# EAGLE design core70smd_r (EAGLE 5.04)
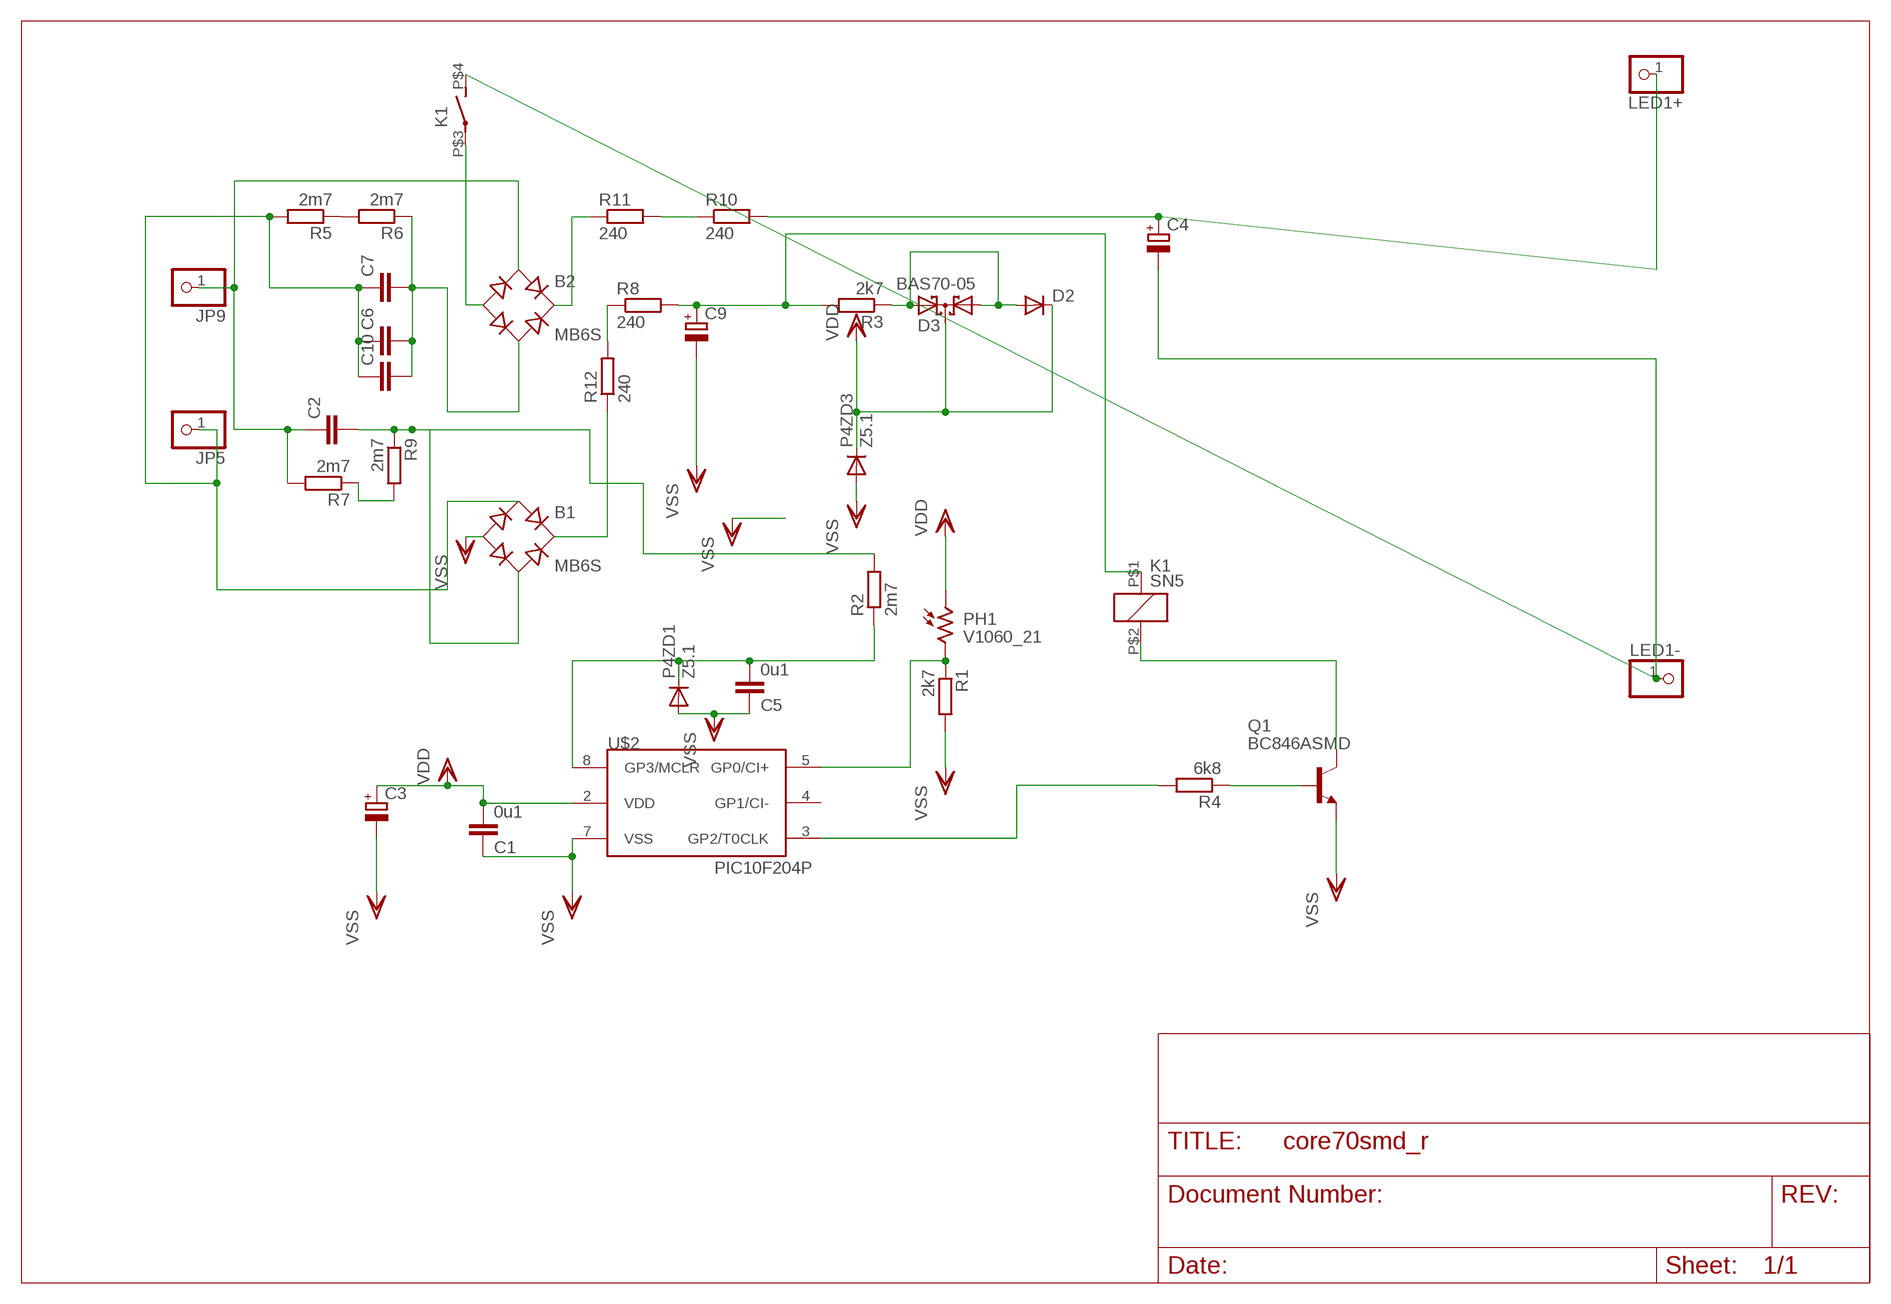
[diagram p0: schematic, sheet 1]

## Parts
B1  MB6S  [SOIC-4]
B2  MB6S  [SOIC-4]
C1  0u1  C-EUC1206  [C1206]
C2  C-EUC4564  [C4564]
C3  CPOL-EUD  [PANASONIC_D]
C4  CPOL-EUSMCE  [SMC_E]
C5  0u1  C-EUC1206  [C1206]
C6  C-EUC4564  [C4564]
C7  C-EUC4564  [C4564]
C9  CPOL-EUSMCD  [SMC_D]
C10  C-EUC4564  [C4564]
D2  DIODE-MINIMELF  [MINIMELF]
D3  BAS70-05  [SOT23]
JP5  PINHD-1X1  [1X01]
JP9  PINHD-1X1  [1X01]
K1  SN5  [HU]
LED1+  PINHD-1X1  [1X01]
LED1-  PINHD-1X1  [1X01]
P4ZD1  Z5.1  DIODE-MINIMELF  [MINIMELF]
P4ZD3  Z5.1  DIODE-MINIMELF  [MINIMELF]
PH1  V1060_21  [TO-5_V10]
Q1  BC846ASMD  [SOT23]
R1  2k7  R-EU_R1206  [R1206]
R2  2m7  R-EU_R1206  [R1206]
R3  2k7  R-EU_MELF0207R  [MINI_MELF-0207R]
R4  6k8  R-EU_R1206  [R1206]
R5  2m7  R-EU_R1210  [R1210]
R6  2m7  R-EU_R1210  [R1210]
R7  2m7  R-EU_R1210  [R1210]
R8  240  R-EU_R1210  [R1210]
R9  2m7  R-EU_R1210  [R1210]
R10  240  R-EU_R2010  [R2010]
R11  240  R-EU_R2010  [R2010]
R12  240  R-EU_R1210  [R1210]
U$2  PIC10F204P  [DIL8]

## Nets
AC1: B1.~1(AC1) C6.1 C7.1 C10.1 JP5.1 R5.2
AC2: B2.~1(AC1) C2.1 JP9.1 R7.2
CBIG: B2.~2(AC2) C6.2 C7.2 C10.2 R6.1
CSMALL: B1.~2(AC2) C2.2 R2.2 R9.1
D+: C4.+ LED1+.1 R10.2
D-: C4.- K1.P$4(2:S) LED1-.1
DR+: C9.+ K1.P$1 R3.2 R8.2
N$1: C5.2 P4ZD1.C R2.1 U$2.8(GP3/MCLR)
N$2: R5.1 R6.2
N$3: R7.1 R9.2
N$4: R8.1 R12.2
N$5: D2.A D3.1(A1) D3.2(A2) R3.1
N$6: R10.1 R11.2
N$9: B2.- K1.P$3(2:P)
N$11: B2.+ R11.1
N$12: Q1.1(B) R4.1
N$13: K1.P$2 Q1.3(C)
N$15: R4.2 U$2.3(GP2/T0CLK)
N$17: PH1.2 R1.1 U$2.5(GP0/CI+)
RECDR+: B1.+ R12.1
VDD: C1.2 C3.+ D2.C D3.3(C) P4ZD3.C PH1.1 U$2.2(VDD)
VSS: B1.- C1.1 C3.- C5.1 C9.- P4ZD1.A P4ZD3.A Q1.2(E) R1.2 U$2.7(VSS)
Unconnected: U$2.4(GP1/CI-)

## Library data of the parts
B1 B2 = rectifier:MB*S: Bridge Rectifier Source: http://www.fairchildsemi.com/ds/MB/MB6S.pdf
C1 C5 = rcl:C-EU: CAPACITOR, European symbol
C2 C6 C7 C10 = rcl-2:C-EU: CAPACITOR, European symbol
C3 C4 C9 = rcl-2:CPOL-EU: POLARIZED CAPACITOR, European symbol
D2 P4ZD1 P4ZD3 = diode:DIODE-: DIODE
D3 = diode:BAS70-05: Silicon Schottky Diodes General-purpose diode for high-speed switching
JP5 JP9 LED1+ LED1- = pinhead(2):PINHD-1X1: PIN HEADER
K1 = relay:SN*: Slim PCB Relay 1 pole 6 A SCHRACK Source: http://www.schrack.com/.. 5815.pdf
PH1 = photo-elements:?1060*: Sensor Street Light control
Q1 = transistor-npn:BC846*: NPN Transistor
R1-R12 = rcl-2:R-EU_: RESISTOR, European symbol
U$2 = microchip-3:PIC10F2*: uPC nW 0,25/0,5k Program Flash memory Comparator

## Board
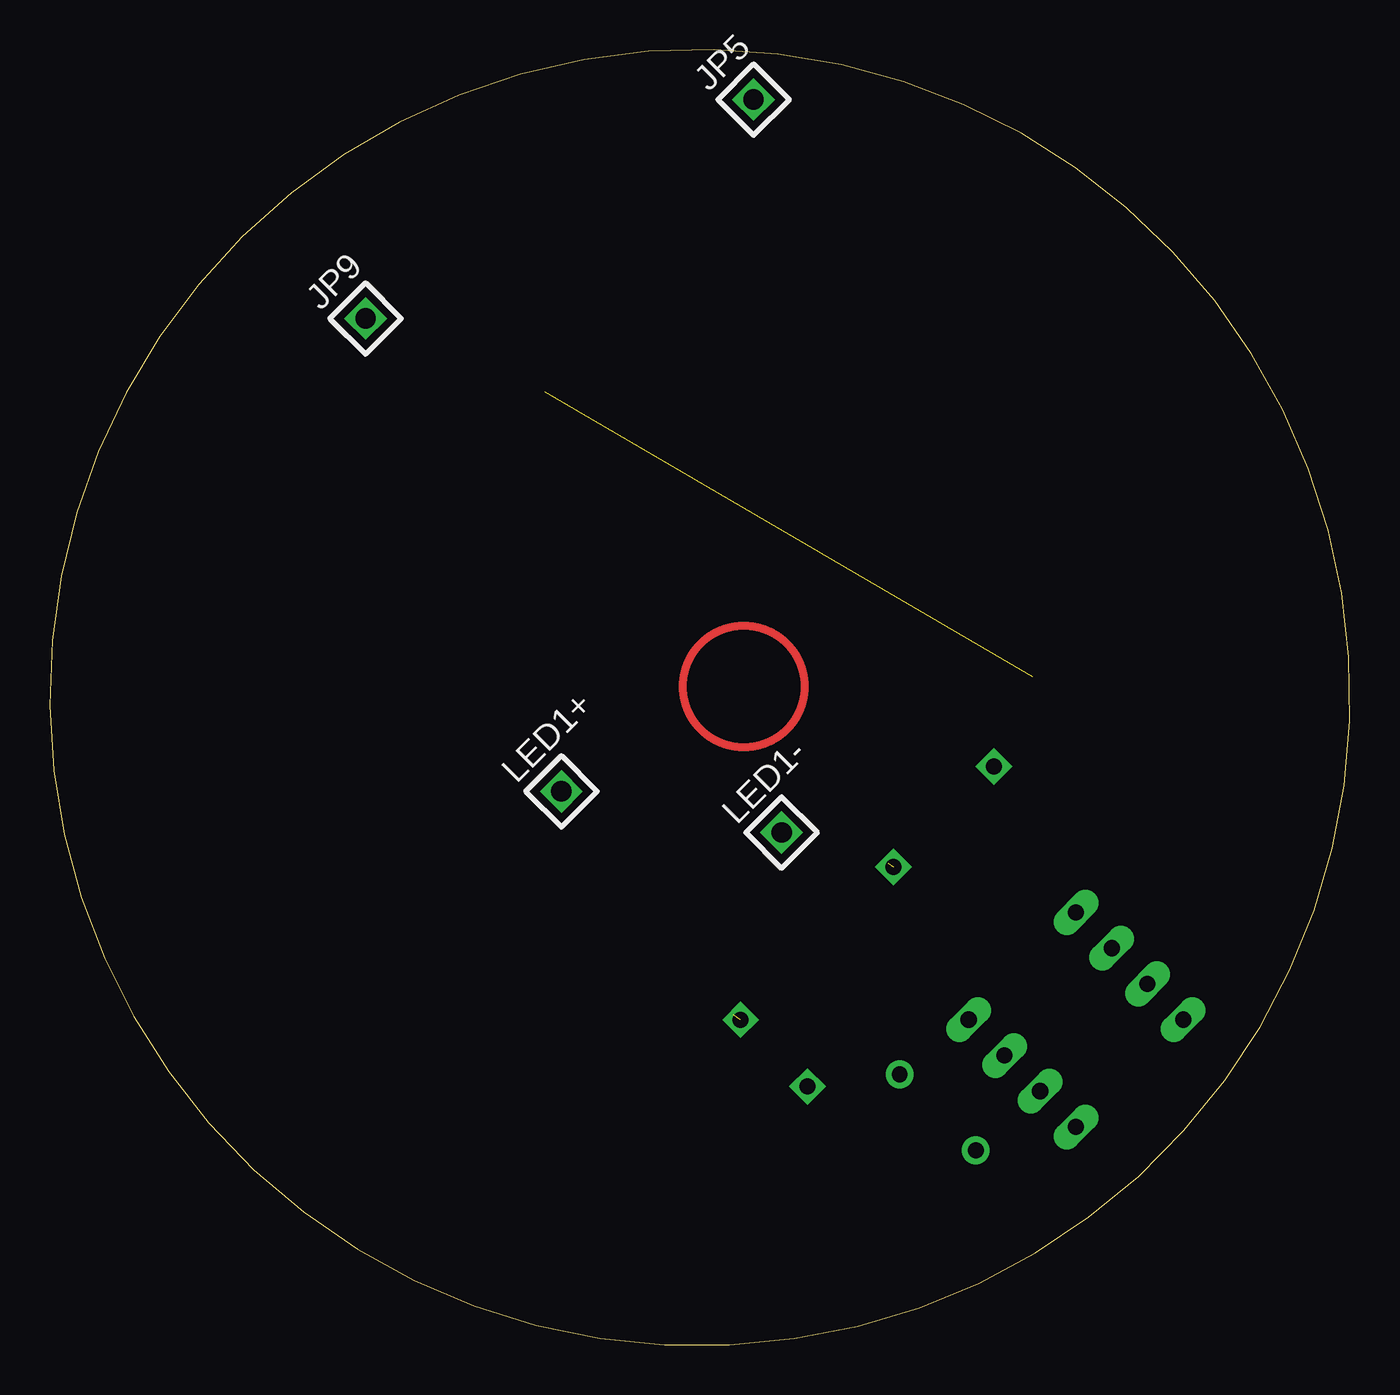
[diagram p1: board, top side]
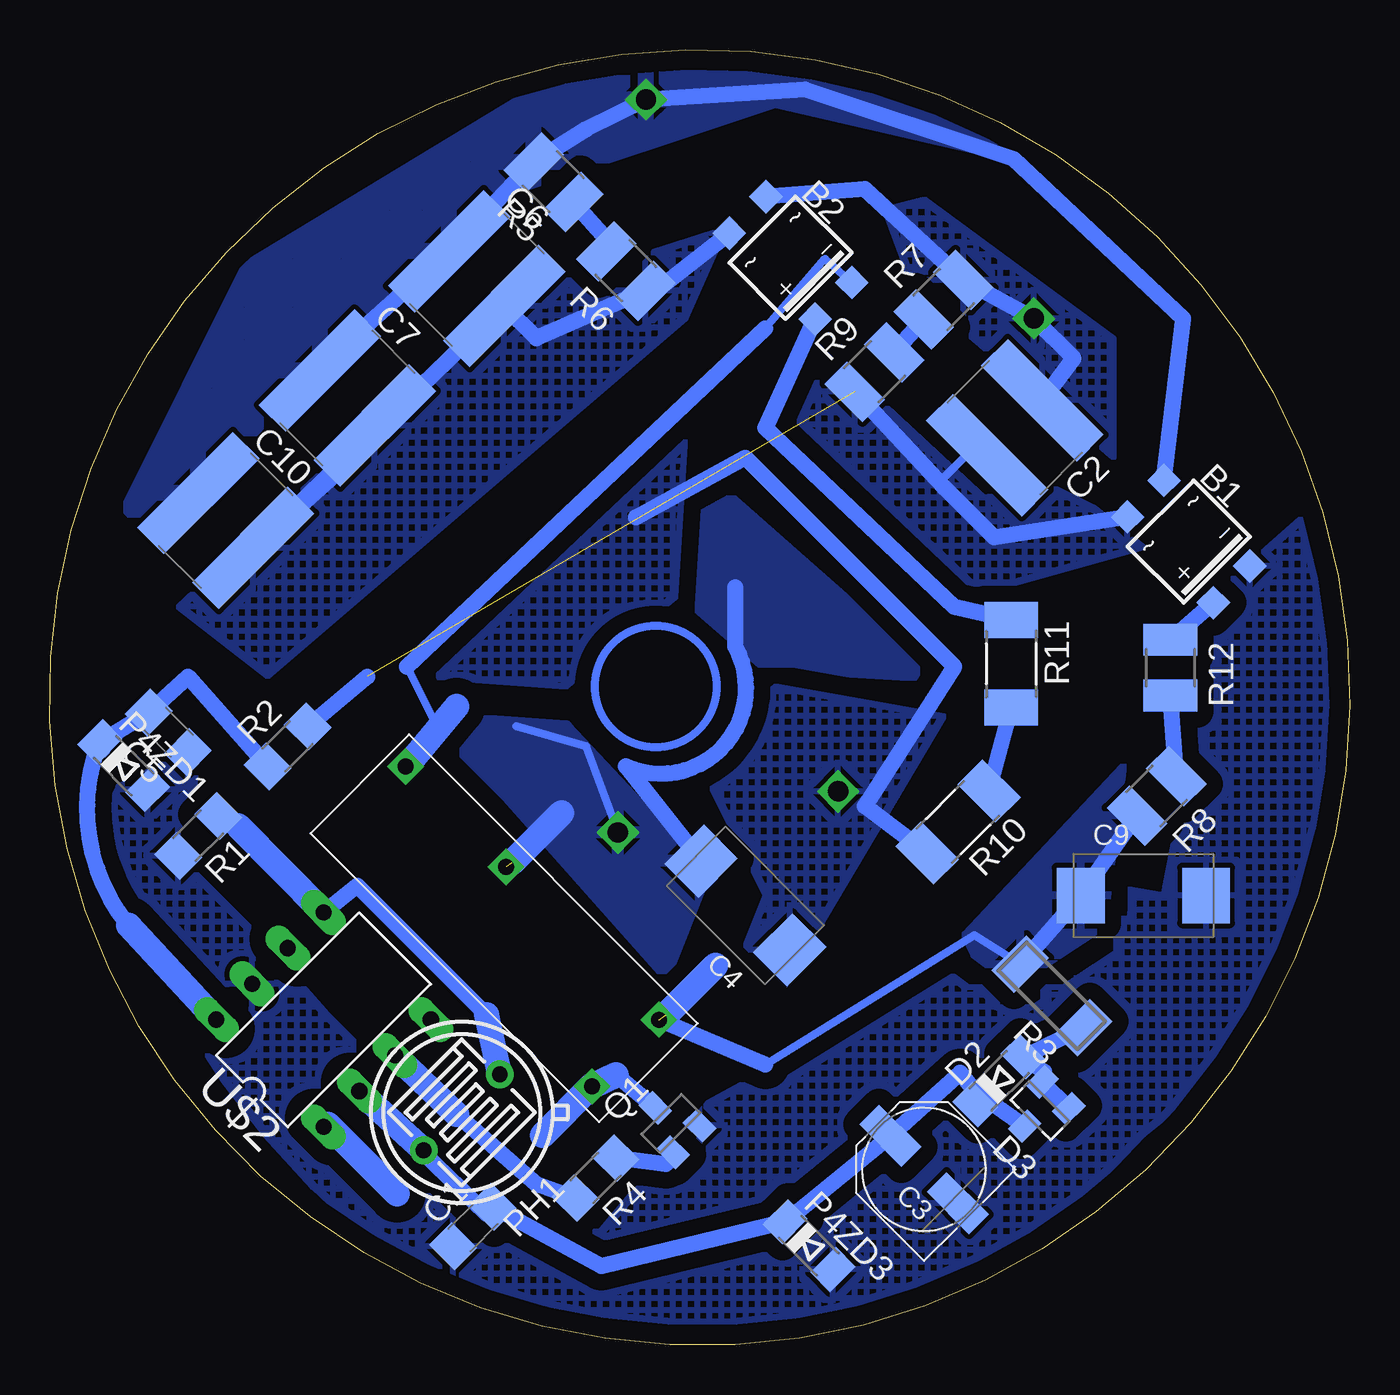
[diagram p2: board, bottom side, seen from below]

Size 65.32 x 65.07 mm. Coordinates in mm from the lower left corner, seen from the top.
Outline: 37.42,0.32 arc171 33.37,65.07 arc190 37.42,0.32
Copper layers (1*16): Top 0.035mm / dielectric 1.5mm / Bottom 0.035mm
Design rules "default": minimum track width 10mil, minimum drill 24mil, track to track 8mil, track to pad 8mil, pad to pad 8mil, via to via 8mil, smd to smd 8mil, copper to edge 40mil, drill to drill 8mil, minimum pad ring 10mil, minimum via ring 8mil, stop-mask expansion 4mil, vias tented up to drill 0mil, thermal gap 10mil

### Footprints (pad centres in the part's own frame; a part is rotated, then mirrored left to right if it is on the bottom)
SOIC-4 = smd 1.2 x 1.2: + 1.3,3.05; - -1.3,3.05; ~1 -1.3,-3.05; ~2 1.3,-3.05
C1206 = smd 1.6 x 1.8: 1 -1.4,0; 2 1.4,0
C4564 = smd 1.9 x 6.8: 1 -1.95,0; 2 1.95,0
PANASONIC_D = smd 3 x 1.4: + 2.4,0; - -2.4,0
SMC_E = smd 2.4 x 2.8: + -3.15,0; - 3.15,0
SMC_D = smd 2.4 x 2.8: + -3.15,0; - 3.15,0
MINIMELF = smd 1.4 x 1.8: A 1.7,0; C -1.7,0
SOT23 = smd 1 x 1.4: 1 -0.95,-1.1; 2 0.95,-1.1; 3 0,1.1
1X01 = drill 1.016 square: 1 0,0
HU = drill 0.8 square: P$1 2.25,-9; P$2 -2.5,-9; P$3 2.25,9; P$4 2.25,1.85
TO-5_V10 = drill 0.8 pad 1.4 round: 1 -2.7,0; 2 2.7,0
R1206 = smd 1.6 x 1.803: 1 -1.422,0; 2 1.422,0
MINI_MELF-0207R = smd 1.6 x 2.5: 1 -2.25,0; 2 2.25,0
R1210 = smd 1.6 x 2.7: 1 -1.4,0; 2 1.4,0
R2010 = smd 1.8 x 2.7: 1 -2.2,0; 2 2.2,0
DIL8 = drill 0.813 long: 1 -3.81,-3.81; 2 -1.27,-3.81; 3 1.27,-3.81; 4 3.81,-3.81; 5 3.81,3.81; 6 1.27,3.81; 7 -1.27,3.81; 8 -3.81,3.81

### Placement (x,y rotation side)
B1  8.09,40.36 225 bottom
B2  28.1,54.62 225 bottom
C1  44.06,5.94 45 bottom
C2  16.83,46.08 225 bottom
C3  21.39,8.81 135 bottom
C4  30.37,22.07 135 bottom
C5  59.37,30.78 135 bottom
C6  43.87,53.57 315 bottom
C7  50.37,47.57 315 bottom
C9  10.37,22.57 0 bottom
C10  56.48,41.42 315 bottom
D2  17.62,13.27 45 bottom
D3  15.56,11.77 135 bottom
JP5  35.37,62.57 45 top
JP9  15.87,51.57 45 top
K1  42.67,21.11 45 bottom
LED1+  25.71,27.81 45 top
LED1-  36.78,25.74 45 top
P4ZD1  61.61,29.1 315 bottom
P4ZD3  27.17,4.98 315 bottom
PH1  44.62,11.67 45 bottom
Q1  34.12,11.12 45 bottom
R1  57.87,25.57 225 bottom
R2  53.37,30.07 45 bottom
R3  14.97,17.54 135 bottom
R4  37.89,8.38 225 bottom
R5  40.01,58.43 135 bottom
R6  36.37,53.96 135 bottom
R7  20.41,52.52 45 bottom
R8  9.7,27.58 225 bottom
R9  23.88,48.88 45 bottom
R10  19.68,26.27 225 bottom
R11  17.01,34.22 270 bottom
R12  9.02,34.02 270 bottom
U$2  51.57,16.34 45 bottom

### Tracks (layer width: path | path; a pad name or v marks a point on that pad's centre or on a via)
AC1
  Bottom 0.813: B1.~1 8.37,51.57 16.87,59.57 27.37,63.07 JP5.1 38.37,61.07 R5.2 C6.1 52.37,48.57 C7.1
  pour Bottom (isolate 0.813, rank 4, hatched): 25.87,65.07 38.87,64.07 55.37,54.07 61.37,42.07 60.37,41.07 42.37,58.07 28.87,62.57 15.87,59.57
AC2
  Bottom 0.813: B2.~1 24.37,58.07 R7.2 JP9.1 13.87,49.57 C2.1
  pour Bottom (isolate 0.813, rank 3, hatched): 23.37,57.07 21.37,57.57 11.87,50.57 11.87,44.57 21.87,53.07
CBIG
  Bottom 0.813: B2.~2 35.37,52.57 R6.1 40.87,50.57 C6.2 C10.2 48.37,46.07 C7.2
  pour Bottom (isolate 0.813, rank 3, hatched): 31.37,56.07 33.37,51.57 54.37,33.57 58.87,37.07 42.37,52.57
CSMALL  (1 unrouted)
  Bottom 0.406: C2.2 19.25,44.71 20.62,43.34
  Bottom 0.813: B1.~2 17.87,40.57 20.37,43.07 R9.1 | R2.2 49.37,33.57
  pour Bottom (isolate 0.813, rank 3, hatched): 25.37,49.07 27.37,48.07 27.87,45.57 19.37,37.57 10.37,40.07 12.87,42.07 14.87,43.07 18.37,42.57
D+
  Bottom 0.813: R10.2 24.37,27.07 19.87,34.07 30.37,44.57 35.87,41.57
  pour Bottom (isolate 0.813, hatched): 39.37,40.07 46.37,33.57 39.37,33.07 33.87,37.57 33.37,45.57
  pour Bottom (isolate 0.813, hatched): 28.37,18.07 20.37,31.57 28.87,33.07 32.87,29.57 29.37,22.57 30.37,20.07
D-  (1 unrouted)
  Bottom 0.406: 41.87,31.07 38.37,30.07 LED1-.1
  Bottom 0.813: C4.- 36.37,29.07 arc-143 30.87,35.07 30.87,38.07
  Bottom 1.27: 42.12,24.22 39.62,26.72
  pour Bottom (isolate 0.813, rank 2): 42.37,27.57 34.37,18.57 32.37,23.57 39.37,31.07 46.37,31.57
  pour Bottom (isolate 0.813, rank 2): 24.37,36.57 32.87,44.07 33.37,37.57 29.37,34.07 20.87,33.57
DR+  (1 unrouted)
  Bottom 0.406: 29.37,14.07 18.87,20.57 R3.2
  Bottom 0.813: R8.2 C9.+ R3.2 | 29.37,14.07 K1.P$1
  Bottom 1.27: 31.87,19.07 34.37,16.57
  pour Bottom: 11.37,29.07 19.37,20.57 18.87,19.57 16.87,18.07 12.37,21.07
N$1
  Bottom 0.813: R2.1 58.37,33.57 C5.2 P4ZD1.C arc-60 61.37,21.07
  Bottom 1.27: U$2.8 61.37,21.07 | P4ZD1.C 62.87,30.07
N$2
  Bottom 0.813: R5.1 37.37,55.57 R6.2
N$3
  Bottom 0.813: R7.1 R9.2
N$4
  Bottom 0.813: R8.1 R12.2
N$5
  Bottom 0.813: R3.1 D2.A 15.37,13.72 D3.2 D3.1
N$6
  Bottom 0.813: R10.1 R11.2
N$8
  Bottom 1.27: 47.87,7.57 51.37,11.07
N$9
  Bottom 0.406: B2.- 26.37,54.57 29.37,51.07 | 47.37,34.07 45.87,31.07 K1.P$3
  Bottom 0.813: 47.37,34.07 29.37,51.07
N$11
  Bottom 0.813: B2.+ 29.37,46.07 19.87,37.07 R11.1
N$12
  Bottom 0.813: R4.1 34.37,9.07 Q1.1
N$13
  Bottom 0.813: Q1.3 36.87,13.57
  Bottom 1.27: 36.87,13.57 K1.P$2
N$14
  Bottom 1.27: 47.37,29.07 44.87,32.07
N$15
  Bottom 0.813: 44.87,11.57 40.87,8.07 R4.2
  Bottom 1.27: 44.87,11.57 U$2.3
N$16
  Bottom 1.27: 40.57,10.52 38.07,13.02
N$17
  Bottom 0.813: 43.37,16.57 49.87,23.07 U$2.5 | 55.87,26.07 R1.1
  Bottom 1.27: PH1.2 43.37,16.57 | U$2.5 55.87,26.07
RECDR+
  Bottom 0.813: R12.1 B1.+
VDD
  Bottom 0.813: 18.85,12.74 D2.C | 18.85,12.74 19.57,13.67 C3.+ P4ZD3.C 37.61,3.95 C1.2 43.37,6.57 U$2.2 | D3.3 18.85,12.74
  Bottom 1.27: U$2.2 PH1.1
VSS
  pour Bottom (isolate 0.813, rank 4, hatched): 1.87,42.07 6.37,38.07 9.37,22.57 12.27,23.07 32.22,12.17 37.72,5.62 47.52,12.72 51.37,16.57 54.87,20.57 58.37,24.07 57.87,30.07 61.87,28.07 62.87,26.07 arc-37 46.77,3.27 arc-8 29.77,0.27 arc-42 10.37,10.57 arc-47 0.37,27.57
(copper drawn outside any net)
  shapes: Bottom circle x1, Top circle x1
